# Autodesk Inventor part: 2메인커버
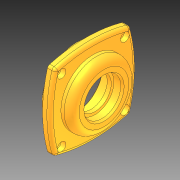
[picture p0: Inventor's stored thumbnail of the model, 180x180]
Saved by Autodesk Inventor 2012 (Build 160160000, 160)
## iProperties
Created: 2012-07
Part Number: 2메인커버
Material: Default
Document SubType Name: Modeling
Designer: JANG KYOUNG-IL
Density: 1 g/cm^3
Author: JANG KYOUNG-IL
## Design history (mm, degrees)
node "작업축1"
node "작업 평면2"
node "작업점1"
sketch "스케치12"
  geometry: L1 (-46.5, 57.5)-(-72.5, 57.5); L2 (-46.5, 90)-(-55.5, 90); L3 (-55.5, 90)-(-55.5, 87.5); L4 (-55.5, 87.5)-(-72.5, 87.5); L5 (-72.5, 87.5)-(-72.5, 75); L6 (-72.5, 75)-(-64.2, 75); L7 (-64.2, 75)-(-64.2, 72.5); L8 (-64.2, 72.5)-(-60.5, 72.5); L9 (-60.5, 72.5)-(-60.5, 81); L10 (-60.5, 81)-(-46.5, 81); L11 (-46.5, 81)-(-46.5, 90); 1 further point
  constraints: 22 end point, 8 parallel, 4 point on line, 2 vertical, 1 horizontal
  dimensions: "d87" = 8.3 horizontal distance of L7.end L5.end; "d88" = 14 horizontal distance of L8.end L10.end; "d89" = 30 diameter of L8 L1; "d90" = 35 diameter of L6 L1; "d91" = 47 diameter of L10 L1; "d92" = 65 diameter of L2 L1; "d93" = 60 diameter of L4 L1; "d95" = 9 distance of L2.start L2.end; "d96" = 26 horizontal distance of L4.end L2.start
revolve "회전1" sketch "스케치12" stored, may be unused: angle "d97" = 90 deg
sketch "스케치13"
  geometry: L1 (-35.002, 92.502)-(35.002, 92.502); L2 (35.002, 92.502)-(35.002, 22.498); L3 (35.002, 22.498)-(-35.002, 22.498); L4 (-35.002, 22.498)-(-35.002, 92.502); C1 r 23.5 at (0, 57.5) reference; A1 r 125.055 centre (0, -27.555) between (35.002, 92.502) and (-35.002, 92.502); A2 r 125.055 centre (0, 142.555) between (-35.002, 22.498) and (35.002, 22.498); A3 r 125.055 centre (85.055, 57.5) between (-35.002, 92.502) and (-35.002, 22.498); A4 r 125.055 centre (-85.055, 57.5) between (35.002, 22.498) and (35.002, 92.502); 4 further points
  constraints: 8 end point, 8 point on circle, 4 centre point, 2 equal radius, 2 midpoint, 2 parallel, 2 perpendicular, 1 horizontal, 1 horizontal alignment, 1 vertical alignment
  dimensions: "d98" = 99 distance of L1.end L3.end; "d99" = 80 dimension on A2 A1; "d100" = 80 dimension on A4 A3
extrude "돌출10" join sketch "스케치13" distance "d101" = 7; taper "d102" = 0 deg
fillet "모깎기7" dims "d103" = 7
chamfer "모따기2" distance "d104" = 2; stored, may be unused: second distance "d105" = 2, angle "d106" = 30 deg
fillet "모깎기8" dims "d107" = 0.3
chamfer "모따기3" distance "d108" = 1; stored, may be unused: second distance "d109" = 2, angle "d110" = 30 deg
sketch "스케치14"
  geometry: L1 (-57.5, 0)-(-99, 0); A1 r 41.5 centre (-57.5, 0) between (-86.845, 29.345) and (-99, 0); 2 further points
  constraints: 2 end point, 2 point on circle, 1 centre point, 1 coincident, 1 horizontal
  dimensions: "d111" = 45 deg dimension on point (-57.5, 0) L1.end A1.start; "d120" = 83 diameter of A1
hole "구멍3" sketch "스케치14" at (-57.5, 0), (-86.845, 29.345) diameter "d112" = 4.5; stored, may be unused: countersink angle "d116" = 90 deg, drill point angle "d118" = 118 deg; dims "d113" = 6, "d114" = 8, "d115" = 4.4, "d117" = 8
node "작업 평면3"
fillet "모깎기9" dims "d121" = 3
node "솔리드1"
mirror "대칭3"
mirror "대칭4"
node "솔리드3"
other parameters: "d83" = 55.5, "d119" = 90 deg
